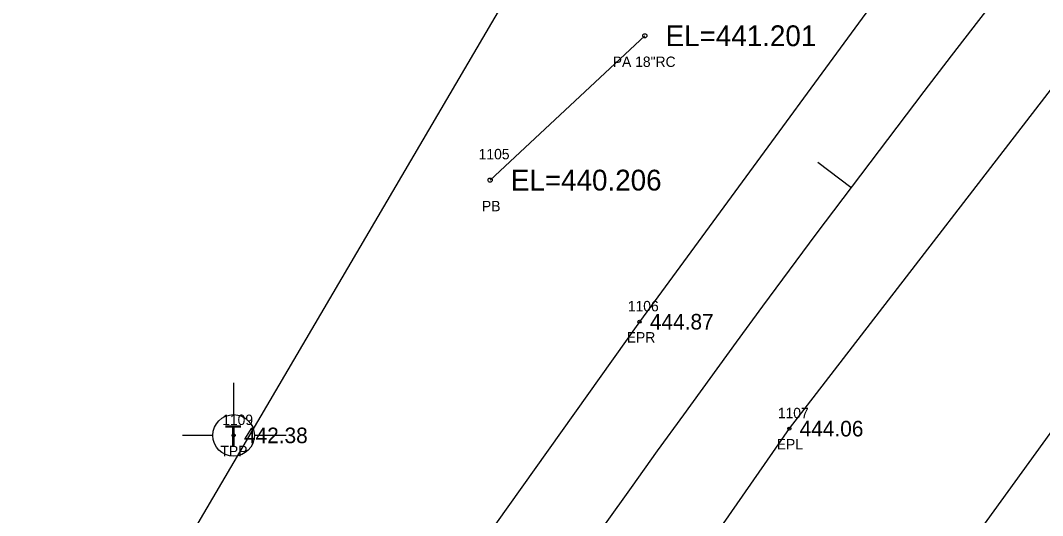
# Model space of a CAD drawing. Extents: x 1762456 to 1764480, y 822234 to 826541.
# Drawn here: x 1763452.5 to 1763550.9, y 824859.3 to 824906.9 of the extents above; entities that cross this region are included whole.
import ezdxf

# ---------------------------------------------------------------- set-up
doc = ezdxf.new("R2010")
doc.units = 0
for name, color, linetype in [('RD_EX_DR_Pipe', 7, 'Continuous'), ('RD_EX_DR_Pipe_txCode', 7, 'Continuous'), ('RD_EX_Road', 7, 'Continuous'), ('RD_EX_Road_txCode', 7, 'Continuous'), ('RD_EX_TX_Road_ELEV', 7, 'Continuous'), ('RD_EX_TX_UT_ELEV', 7, 'Continuous'), ('RD_EX_UT', 7, 'Continuous'), ('RD_EX_UT_txCode', 7, 'Continuous'), ('RD_EX_VEG', 7, 'Continuous'), ('RD_HC_Cl', 7, 'Continuous'), ('RD_HC_Data_Tic', 7, 'Continuous'), ('RD_SMD_Locator', 7, 'Continuous'), ('RD_TX_Pipe_ElevEX', 7, 'Continuous')]:
    doc.layers.add(name, color=color, linetype=linetype)

msp = doc.modelspace()

# ---------------------------------------------------------------- linework, layer by layer
at = {"layer": 'RD_EX_DR_Pipe'}
msp.add_line((1763512.625, 824905.463), (1763497.737, 824891.578), dxfattribs=at)
at = {"layer": 'RD_EX_Road'}
for points in [[(1763951.028, 825365.438), (1763882.121, 825291.587), (1763813.301, 825217.444), (1763784.22, 825184.639), (1763754.382, 825152.478), (1763744.668, 825142.842), (1763675.267, 825070.174), (1763607.457, 824995.533), (1763574.265, 824958.093), (1763542.372, 824919.201), (1763512.113, 824877.957), (1763483.203, 824837.348)], [(1763963.891, 825353.592), (1763895.682, 825279.081), (1763827.34, 825205.219), (1763758.38, 825131.335), (1763689.427, 825057.327), (1763653.535, 825018.753), (1763637.74, 825000.803), (1763620.709, 824983.807), (1763588.782, 824946.603), (1763557.13, 824907.379), (1763526.523, 824867.674), (1763498.427, 824827.249)]]:
    msp.add_lwpolyline(points, dxfattribs=at)
at = {"layer": 'RD_EX_UT'}
for p, q in [((1763473.057, 824872.093), (1763473.057, 824869.024)), ((1763468.127, 824867.039), (1763471.057, 824867.039)), ((1763475.057, 824867.039), (1763478.127, 824867.039))]:
    msp.add_line(p, q, dxfattribs=at)
msp.add_circle((1763473.057, 824867.024), 2, dxfattribs=at)
at = {"layer": 'RD_EX_VEG'}
for points in [[(1763566.804, 824996.313), (1763552.477, 824977.489), (1763517.791, 824940.661), (1763441.019, 824809.917), (1763409.908, 824765.774), (1763387.308, 824719.585), (1763364.334, 824675.154), (1763345.198, 824627.763), (1763325.757, 824580.46), (1763306.335, 824535.898), (1763266.935, 824443.239), (1763235.968, 824345.204), (1763198.019, 824250.85), (1763166.498, 824157.968)], [(1763654.174, 824981.39), (1763637.841, 824967.614), (1763603.039, 824934.549), (1763572.899, 824896.618), (1763543.523, 824856.037), (1763489.474, 824779.675), (1763459.285, 824736.58), (1763444.879, 824693.265), (1763423.623, 824647.114), (1763401.17, 824604.963), (1763396.878, 824581.151)]]:
    msp.add_lwpolyline(points, dxfattribs=at)
at = {"layer": 'RD_HC_Cl'}
msp.add_arc((1764677.021, 824029.626), 1432.392, 137.053176, 159.117629, dxfattribs=at)
at = {"layer": 'RD_HC_Data_Tic'}
msp.add_line((1763532.454, 824890.853), (1763529.257, 824893.258), dxfattribs=at)
at = {"layer": 'RD_SMD_Locator'}
for centre, radius in [((1763512.625, 824905.463), 0.2), ((1763497.737, 824891.578), 0.2), ((1763512.113, 824877.957), 0.15), ((1763526.523, 824867.674), 0.15), ((1763473.057, 824867.024), 0.15)]:
    msp.add_circle(centre, radius, dxfattribs=at)

# ---------------------------------------------------------------- texts
at = {"layer": 'RD_EX_DR_Pipe_txCode'}
for s, p in [('PA 18"RC', (1763509.539, 824902.463)), ('1105', (1763496.635, 824893.578)), ('PB', (1763496.957, 824888.578))]:
    msp.add_text(s, height=1, dxfattribs=at).set_placement(p)
at = {"layer": 'RD_EX_Road_txCode'}
for s, p in [('1106', (1763510.987, 824878.957)), ('EPR', (1763510.885, 824875.957)), ('1107', (1763525.42, 824868.674)), ('EPL', (1763525.318, 824865.674))]:
    msp.add_text(s, height=1, dxfattribs=at).set_placement(p)
at = {"layer": 'RD_EX_TX_Road_ELEV'}
for s, p in [('444.87', (1763513.113, 824877.207)), ('444.06', (1763527.523, 824866.924))]:
    msp.add_text(s, height=1.5, dxfattribs=at).set_placement(p)
at = {"layer": 'RD_EX_TX_UT_ELEV'}
msp.add_text('442.38', height=1.5, dxfattribs=at).set_placement((1763474.057, 824866.274))
at = {"layer": 'RD_EX_UT'}
msp.add_text('T', height=2, dxfattribs=at).set_placement((1763472.208, 824865.976))
at = {"layer": 'RD_EX_UT_txCode'}
for s, p in [('1109', (1763471.955, 824868.024)), ('TPP', (1763471.789, 824865.024))]:
    msp.add_text(s, height=1, dxfattribs=at).set_placement(p)
at = {"layer": 'RD_TX_Pipe_ElevEX'}
for s, p in [('EL=441.201', (1763514.625, 824904.463)), ('EL=440.206', (1763499.737, 824890.578))]:
    msp.add_text(s, height=2, dxfattribs=at).set_placement(p)

doc.saveas('drawing.dxf')
